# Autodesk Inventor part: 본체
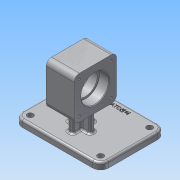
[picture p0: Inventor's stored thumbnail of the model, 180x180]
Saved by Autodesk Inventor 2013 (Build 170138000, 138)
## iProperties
Created: 2020-11
Part Number: 본체
Material: 알루미늄 6061
Document SubType Name: Modeling
Designer: user
Density: 2.71 g/cm^3
Mass: 681.977 g
Surface Area: 540.703 cm^2
Volume: 251.652 cm^3
Author: user
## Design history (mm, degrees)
sketch "스케치1"
  geometry: L1 (-37, 65)-(37, 65); L2 (49, 53)-(49, -53); L3 (37, -65)-(-37, -65); L4 (-49, -53)-(-49, 53); L5 (-49, 65)-(49, -65); L6 (49, 65)-(-49, -65); A1 r 12 centre (-37, 53) between (-37, 65) and (-49, 53); A2 r 12 centre (37, 53) between (49, 53) and (37, 65); A3 r 12 centre (37, -53) between (37, -65) and (49, -53); A4 r 12 centre (-37, -53) between (-49, -53) and (-37, -65); 1 further point
  constraints: 12 end point, 8 point on circle, 8 point on line, 8 tangent, 4 centre point, 2 equal radius, 2 midpoint, 2 parallel, 1 horizontal, 1 perpendicular
  dimensions: "d0" = 98 distance of L5.end L6.end; "d1" = 130 distance of L6.start L5.end; "d2" = 12 radius of A1; "d3" = 12 radius of A3
extrude "돌출1" new body sketch "스케치1" distance "d4" = 10; taper "d5" = 0 deg
node "작업 평면1"
sketch "스케치2"
  geometry: L1 (-12, 0)-(-12, 10) reference; L2 (-12, 10)-(86, 10) reference; L3 (86, 10)-(86, 0) reference; L4 (86, 0)-(-12, 0) reference; L5 (18, 102)-(82, 102); L6 (82, 102)-(82, 38); L7 (82, 38)-(18, 38); L8 (18, 38)-(18, 102); L9 (18, 102)-(82, 38); L10 (82, 102)-(18, 38); 2 further points
  constraints: 12 end point, 2 midpoint, 2 parallel, 1 horizontal, 1 perpendicular
  dimensions: "d6" = 64 distance of L6.end L7.end; "d7" = 64 distance of L5.end L6.end; "d9" = 70 distance from line of L4 point (50, 70); "d21" = 62 distance from line of L1 point (50, 70)
extrude "돌출2" join sketch "스케치2" stored distance "d10" = 42; taper "d11" = 0 deg
sketch "스케치3"
  geometry: L1 (-37, -65)-(37, -65) reference; L2 (49, -53)-(49, 53) reference; L3 (-49, -53)-(-49, 53) reference; L4 (-37, 65)-(37, 65) reference; L5 (49, 53)-(49, -53) reference; L6 (37, -65)-(-37, -65) reference; L7 (-9, -17)-(-17, -17); L8 (-17, -17)-(-17, 17); L9 (-17, 17)-(-9, 17); L10 (-9, 17)-(-9, -17); L11 (-9, -17)-(-17, 17); L12 (-17, -17)-(-9, 17); L13 (4, -4)-(-30, -4); L14 (-30, -4)-(-30, 4); L15 (-30, 4)-(4, 4); L16 (4, 4)-(4, -4); L17 (4, -4)-(-30, 4); L18 (-30, -4)-(4, 4); A1 r 12 centre (-37, -53) between (-49, -53) and (-37, -65) reference; A2 r 12 centre (-37, 53) between (-37, 65) and (-49, 53) reference; A3 r 12 centre (37, 53) between (49, 53) and (37, 65) reference; A4 r 12 centre (37, -53) between (37, -65) and (49, -53) reference; 4 further points
  constraints: 24 end point, 6 midpoint, 4 parallel, 2 horizontal, 2 perpendicular
  dimensions: "d12" = 8 distance of L8.end L9.end; "d13" = 34 distance of L7.end L8.end; "d14" = 65 distance from line of L1 point (-13, 0); "d15" = 62 distance from line of L2 point (-13, 0); "d16" = 34 distance of L14.end L15.end; "d17" = 8 distance of L13.end L14.end
extrude "돌출3" join sketch "스케치3" distance "d18" = 42; taper "d19" = 0 deg
node "작업 평면2"
sketch "스케치4"
  geometry: L1 (86, -28)-(86, -38) reference; L2 (86, -38)-(-44, -38) reference; L3 (-44, -38)-(-44, -28) reference; L4 (-44, -28)-(4, -28) reference; L5 (4, -28)-(4, 0) reference; L6 (4, 0)-(0, 0) reference; L7 (0, 0)-(0, 64) reference; L8 (0, 64)-(42, 64) reference; L9 (42, 64)-(42, 0) reference; L10 (42, 0)-(38, 0) reference; L11 (38, 0)-(38, -28) reference; L12 (38, -28)-(86, -28) reference; L13 (0, 53)-(14.7, 53); L14 (15, 52.7)-(15, 50); L15 (15, 50)-(27, 50); L16 (27, 50)-(27, 52.7); L17 (27.3, 53)-(42, 53); L18 (0, 53)-(0, 32); L19 (0, 32)-(42, 32); L20 (42, 32)-(42, 53); A1 r 0.3 centre (14.7, 52.7) between (15, 52.7) and (14.7, 53); A2 r 0.3 centre (27.3, 52.7) between (27.3, 53) and (27, 52.7); 3 further points
  constraints: 16 end point, 6 point on line, 4 point on circle, 4 tangent, 3 parallel, 2 centre point, 2 collinear, 2 midpoint, 1 equal radius, 1 perpendicular
  dimensions: "d22" = 15 distance of L13.start point (15, 53); "d24" = 15 distance of point (27, 53) L17.end; "d25" = 70 distance between parallel lines of L2 L19 (derived); "d26" = 42 diameter of L13 L19; "d27" = 42 diameter of L17 L19; "d28" = 36 diameter of L15 L19; "d29" = 0.3 radius of A1
revolve "회전1" sketch "스케치4" stored, may be unused: angle "d30" = 90 deg
sketch "스케치5"
  geometry: L1 (-82, 38)-(-82, 102) reference; L2 (-82, 102)-(-18, 102) reference; L3 (-18, 102)-(-18, 38) reference; L4 (-18, 38)-(-82, 38) reference; L5 (12, 10)-(12, 0) reference; L6 (12, 0)-(-86, 0) reference; L7 (-86, 0)-(-86, 10) reference; L8 (-86, 10)-(12, 10) reference; L9 (-74, 94)-(-26, 94); L10 (-26, 94)-(-26, 46); L11 (-26, 46)-(-74, 46); L12 (-74, 46)-(-74, 94); L13 (-74, 94)-(-26, 46); L14 (-26, 94)-(-74, 46); C1 r 21 at (-50, 70) reference; 5 further points
  constraints: 12 end point, 4 coincident, 2 midpoint, 2 parallel, 1 horizontal, 1 perpendicular
  dimensions: "d31" = 48 distance of L10.end L11.end; "d32" = 48 distance of L9.end L10.end
hole "구멍1" sketch "스케치5" at (-74, 94), (-74, 46), (-26, 46), (-26, 94) diameter "d33" = 3.242; stored, may be unused: countersink angle "d37" = 90 deg, drill point angle "d39" = 118 deg; dims "d34" = 8, "d35" = 4, "d36" = 2, "d38" = 10
sketch "스케치6"
  geometry: A1 r 12 centre (37, -53) between (37, -65) and (49, -53) reference; A2 r 12 centre (37, 53) between (49, 53) and (37, 65) reference; A3 r 12 centre (-37, 53) between (-37, 65) and (-49, 53) reference; A4 r 12 centre (-37, -53) between (-49, -53) and (-37, -65) reference; 1 further point
hole "구멍2" sketch "스케치6" at (-37, 53), (-37, -53), (37, -53), (37, 53) diameter "d40" = 9; stored, may be unused: countersink angle "d44" = 90 deg, drill point angle "d46" = 118 deg; dims "d41" = 8, "d42" = 4, "d43" = 2, "d45" = 10
fillet "모깎기1" dims "d47" = 8
chamfer "모따기1" distance "d48" = 1; stored, may be unused: second distance "d49" = 2, angle "d50" = 45 deg
fillet "모깎기2" dims "d51" = 3
fillet "모깎기3" dims "d52" = 3
fillet "모깎기4" dims "d53" = 3
sketch "스케치7"
  geometry: L1 (74.619, 9.595)-(74.619, -9.595); L2 (74.619, -9.595)-(3.381, -9.595); L3 (3.381, -9.595)-(3.381, 9.595); L4 (3.381, 9.595)-(74.619, 9.595); L5 (74.619, 0)-(3.381, 0); L6 (39, 9.595)-(39, -9.595); L7 (-37, -65)-(37, -65) reference; L8 (49, -53)-(49, 53) reference; L9 (37, 62)-(-37, 62) reference; L10 (-46, 53)-(-46, -53) reference; L11 (-37, -62)-(37, -62) reference; L12 (46, -53)-(46, 53) reference; L13 (-20, 14)-(-20, 7) reference; L14 (-20, 7)-(-27, 7) reference; L15 (-33, 1)-(-33, -1) reference; L16 (-27, -7)-(-20, -7) reference; L17 (-20, -7)-(-20, -14) reference; L18 (-14, -20)-(-12, -20) reference; L19 (-6, -14)-(-6, -7) reference; L20 (-6, -7)-(1, -7) reference; L21 (7, -1)-(7, 1) reference; L22 (1, 7)-(-6, 7) reference; L23 (-6, 7)-(-6, 14) reference; L24 (-12, 20)-(-14, 20) reference; C1 r 4.5 at (37, -53) reference; C2 r 4.5 at (-37, 53) reference; C3 r 4.5 at (-37, -53) reference; C4 r 4.5 at (37, 53) reference; A1 r 9 centre (37, 53) between (46, 53) and (37, 62) reference; A2 r 9 centre (-37, 53) between (-37, 62) and (-46, 53) reference; A3 r 9 centre (-37, -53) between (-46, -53) and (-37, -62) reference; A4 r 9 centre (37, -53) between (37, -62) and (46, -53) reference; A5 r 6 centre (-27, 1) between (-27, 7) and (-33, 1) reference; A6 r 6 centre (-27, -1) between (-33, -1) and (-27, -7) reference; A7 r 6 centre (-14, -14) between (-20, -14) and (-14, -20) reference; A8 r 6 centre (-12, -14) between (-12, -20) and (-6, -14) reference; A9 r 6 centre (1, -1) between (1, -7) and (7, -1) reference; A10 r 6 centre (1, 1) between (7, 1) and (1, 7) reference; A11 r 6 centre (-12, 14) between (-6, 14) and (-12, 20) reference; A12 r 6 centre (-14, 14) between (-14, 20) and (-20, 14) reference; 1 further point
  constraints: 4 end point, 4 midpoint, 2 other
  dimensions: "d54" = 65 distance between parallel lines of L5 L7; "d55" = 10 distance between parallel lines of L8 L6
feature "엠보싱1" sketch "스케치7" dims "d0" = 98, "d1" = 130, "d2" = 12, "d3" = 12, "d56" = 0.5, "d57" = 0
node "솔리드1"
mirror "대칭1"
node "절단 모서리 투영1"
node "절단 모서리 투영2"
node "절단 모서리 투영3"
node "절단 모서리 투영4"
node "절단 모서리 투영5"
